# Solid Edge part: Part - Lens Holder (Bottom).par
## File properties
Author: hhakima
Template: Normal.par
Last saved by: Houman
Revision: 45
Application: Solid Edge
Material: Aluminum, 6061-T6
Face Style: Aluminum
Fill Style: ANSI38(Aluminum)
Virtual Style: Polished aluminum
Coef. of Thermal Exp: 2.3e-05
Thermal Conductivity: 180.0
Specific Heat: 920.0
Modulus of Elasticity: 68947570000.0
Poission's Ratio: 0.33
Yield Stress: 275790280.0
Ultimate Stress: 310264065.0
Elongation: 0.0
Density: 2712.000 kg/m^3
Accuracy: 0.990
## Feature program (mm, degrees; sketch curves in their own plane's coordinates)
sketch for "unnamed Protrusion 1" plane through (0, 0, 0) normal (0, 0, 1) x-axis (1, 0, 0)
  line (36.7117, 26.7297) -> (36.7117, 1.7297)
  line (36.7117, 1.7297) -> (61.7117, 1.7297)
  line (61.7117, 1.7297) -> (61.7117, 26.7297)
  line (61.7117, 26.7297) -> (36.7117, 26.7297)
extrude "unnamed Protrusion 1" add finite 5 along +normal
sketch for "ExtrudedCutout_3" #1 plane through (49.2117, 14.2297, 5) normal (0, 0, 1) x-axis (0, 1, 0)
sketch for "ExtrudedCutout_3" #2 plane through (49.2117, 14.2297, 5) normal (0, 0, 1) x-axis (0, 1, 0)
extrude "ExtrudedCutout_3" cut finite 4 along -normal
sketch for "ExtrudedCutout_4" plane through (49.2117, 14.2297, 5) normal (0, 0, 1) x-axis (0, 1, 0)
extrude "ExtrudedCutout_4" cut finite 5 along -normal
sketch for "ExtrudedCutout_5" plane through (49.2117, 14.2297, 0) normal (0, 0, -1) x-axis (0, -1, 0)
  line (-2.5, 12.5) -> (-12.5, 12.5)
  line (-2.5, 12.5) -> (-2.5, 8.5)
  line (-2.5, 8.5) -> (-6.5, 5.6992)
  line (-6.5, 5.6992) -> (-6.5, -12.5)
  line (-12.5, -12.5) -> (-6.5, -12.5)
  line (-12.5, 12.5) -> (-12.5, -12.5)
  dimension (linear) = 2.5
  dimension (linear) = 12.5
  dimension (linear) = 12.5
  dimension (linear) = 2.5
extrude "ExtrudedCutout_5" cut finite 5 along -normal
mirror "unnamed Mirror 1" of "ExtrudedCutout_5" about plane through (49.2117, 14.2297, 0.5) normal (0, 1, 0)
extrude "unnamed Cutout 1" cut finite 5
sketch for "unnamed Hole 1" plane through (49.2117, 14.2297, 0) normal (0, 0, -1) x-axis (0, -1, 0)
hole "unnamed Hole 1" through
sketch for "unnamed Hole 2" plane through (49.2117, 14.2297, 0) normal (0, 0, -1) x-axis (0, -1, 0)
  hole centre (-3.5, -10) bore radius 1.35
hole "unnamed Hole 2" through
sketch for "unnamed Hole 3" plane through (49.2117, 14.2297, 0) normal (0, 0, -1) x-axis (0, -1, 0)
  hole centre (3.5, -10) bore radius 1.35
hole "unnamed Hole 3" through
pattern "unnamed Pattern 1" of "unnamed Hole 1", "unnamed Hole 2", "unnamed Hole 3"
sketch for "ExtrudedCutout_23" #1 plane through (49.2117, 14.2297, 0) normal (0, 0, -1) x-axis (0, -1, 0)
  circle centre (5.5, 0) radius 2.5
sketch for "ExtrudedCutout_23" #2 plane through (49.2117, 14.2297, 0) normal (0, 0, -1) x-axis (0, -1, 0)
  circle centre (-5.5, 0) radius 2.5
  dimension (linear) = 5.5
  dimension (linear) = 5.5
extrude "ExtrudedCutout_23" cut finite 4 along -normal
Other named dimensions: "Hole_5": Diameter = 2.7 mm
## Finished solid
Body 1: solid body, 26 faces, 68 edges, 40 vertices.
  Faces by surface: plane 17, cylinder 9
  Edges by curve: line 40, circle 28
Bounding box of the edges (mm): 25.000 x 13.000 x 5.000, from (36.7117, 7.7297, 0) to (61.7117, 20.7297, 5).
Cylindrical faces by radius (mm): R1.35 x3, R2.5 x4, R5.5 x1, R6.25 x1
Planar faces by outward normal: +x 1, +y 3, +z 3, -x 1, -y 3, -z 4, oblique 2
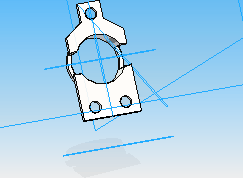
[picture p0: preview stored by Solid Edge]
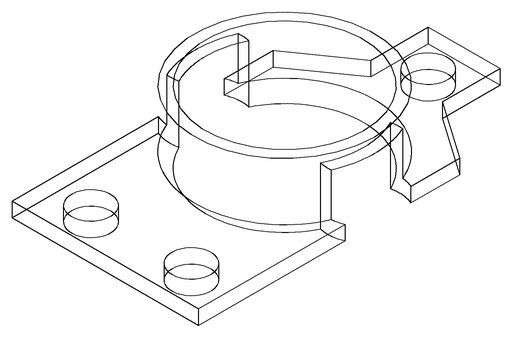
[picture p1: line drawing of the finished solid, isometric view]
